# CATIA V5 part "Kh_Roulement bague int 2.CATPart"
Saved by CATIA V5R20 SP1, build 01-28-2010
Part number: Roulement bague int 2
Bounding box of the stored display mesh (mm): x -12.495 to 12.495, y -12.495 to 12.495, z -10 to 2
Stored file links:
  G:\Khaled_CFAO_2011\SIL\SIL_GR1\tmerino\Khaled\CAD_Thinkmotion\Kh_Roulement bague int 2.CATPart
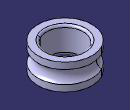
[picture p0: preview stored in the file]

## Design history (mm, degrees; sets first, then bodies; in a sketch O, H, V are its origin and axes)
Body1 (main body)
  Sketch1 on yz-plane, origin (0, 0, 0), H (0, 1, 0), V (0, 0, 1)
    line L1 (8.5, -10) -> (8.5, 2)
    line L2 (8.5, 2) -> (12.5, 2)
    line L3 (8.5, -10) -> (12.5, -10)
    line L4 (12.5, 2) -> (12.5, -1)
    line L5 (12.5, -10) -> (12.5, -7)
    arc A1 centre (14.25, -4) radius 3.4731 from (12.5, -1) to (12.5, -7) ccw
    distance L1 V = 8.5
    length L2 = 4
    length L3 = 4
    length L1 = 12
    length L4 = 3
    length L5 = 3
    vertical: L1 V, L4 V, L5 V
    horizontal: L2 H, L3 H
  Shaft1: profile Sketch1, axis Sketch1.V, angle 360
  Fillet1: radius 1, on face of Shaft1 from Sketch1.L1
